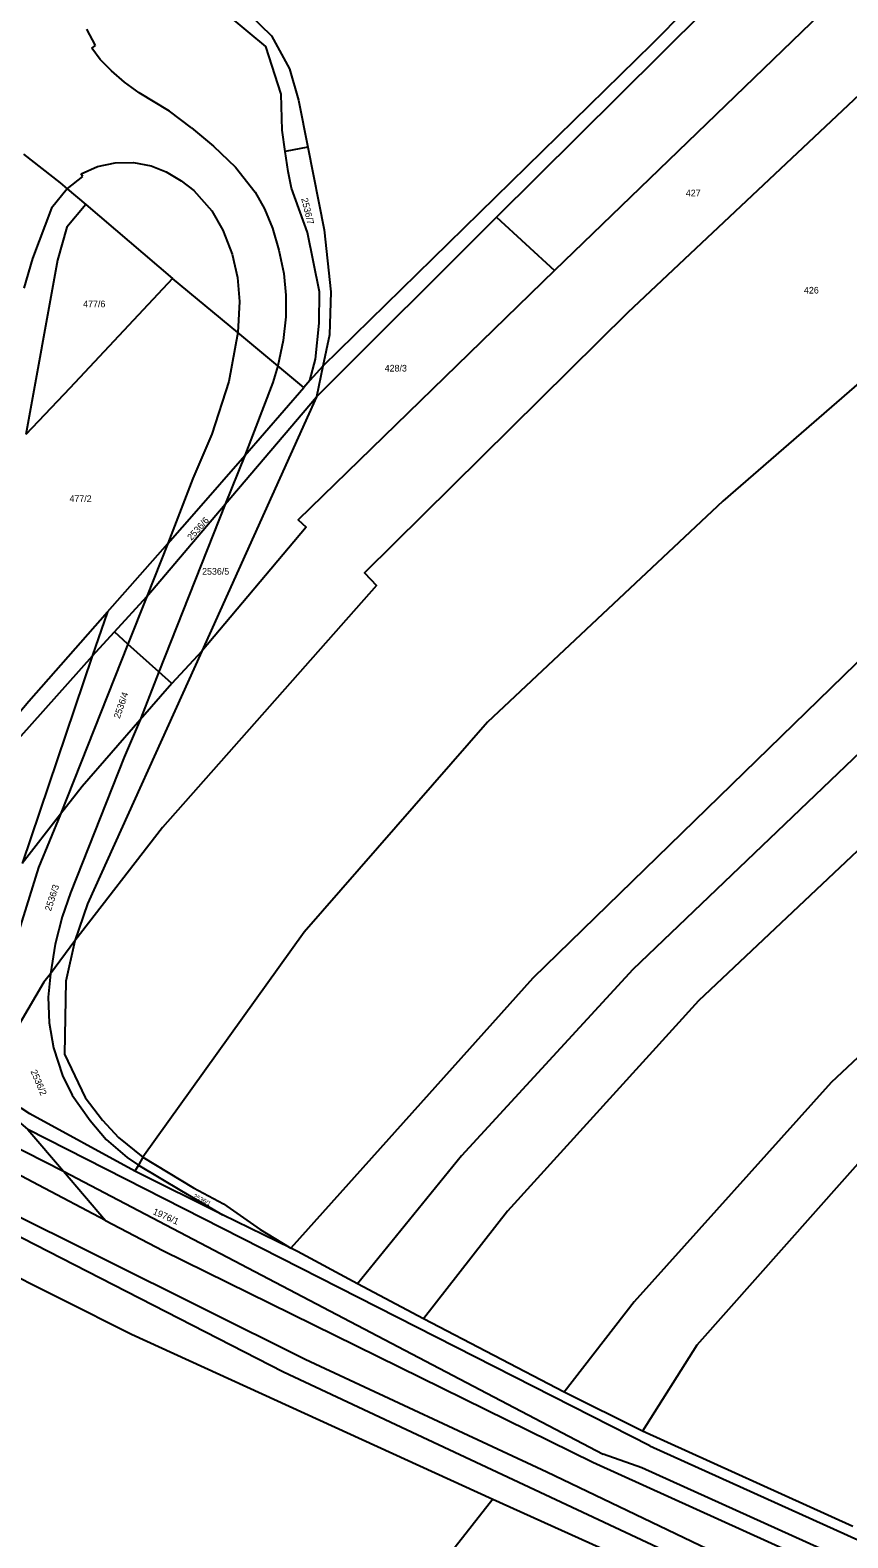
# Model space of a CAD drawing. Extents: x -679220 to -673243, y -1075091 to -1066557.
# Drawn here: x -675395.3 to -675185.8, y -1072555.7 to -1072169.3 of the extents above; entities that cross this region are included whole.
import ezdxf

# ---------------------------------------------------------------- set-up
doc = ezdxf.new("R2010")
doc.units = 0
for name, color, linetype in [('Hranice parcel', 7, 'Continuous'), ('Parcelní čísla', 7, 'Continuous'), ('Poz předměty', 7, 'Continuous'), ('Vnitřní kresba', 7, 'Continuous')]:
    doc.layers.add(name, color=color, linetype=linetype)

msp = doc.modelspace()

# ---------------------------------------------------------------- linework, layer by layer
at = {"layer": 'Hranice parcel'}
for p, q in [((-675324.2, -1072199.3), (-675329.94, -1072200.44)), ((-675381.09, -1072214.03), (-675358.84, -1072232.94)), ((-675321.99, -1072263.33), (-675275.85, -1072217.26)), ((-675275.85, -1072217.26), (-675260.93, -1072230.94)), ((-675320.31, -1072255.48), (-675323.63, -1072259.08)), ((-675320.31, -1072255.48), (-675321.99, -1072263.33)), ((-675323.63, -1072259.08), (-675325.19, -1072260.93)), ((-675321.99, -1072263.33), (-675351.33, -1072328.51)), ((-675375.49, -1072318.41), (-675379.42, -1072329.8)), ((-675379.42, -1072329.8), (-675373.72, -1072323.56)), ((-675379.42, -1072329.8), (-675413.96, -1072368.46)), ((-675379.42, -1072329.8), (-675397.36, -1072382.87)), ((-675351.33, -1072328.51), (-675359.05, -1072336.81)), ((-675294.51, -1072499.65), (-675311.42, -1072490.62)), ((-675258.46, -1072518.44), (-675294.51, -1072499.65)), ((-675238.38, -1072528.41), (-675258.46, -1072518.44)), ((-675184.55, -1072552.8), (-675238.38, -1072528.41))]:
    msp.add_line(p, q, dxfattribs=at)
for points in [[(-675275.85, -1072217.26), (-675244.41, -1072186.09), (-675178.48, -1072120.54), (-675145.94, -1072086.5), (-675117.65, -1072059.4), (-675100.56, -1072044.12)], [(-675329.94, -1072200.44), (-675330.72, -1072194.99), (-675330.99, -1072185.71), (-675334.96, -1072173.49), (-675339.5, -1072169.79), (-675348.13, -1072162.6), (-675353.01, -1072157.19), (-675356.64, -1072151.17), (-675358.93, -1072144.01), (-675360.73, -1072132.39), (-675360.41, -1072126.14), (-675357.75, -1072103.37), (-675354.88, -1072083.03), (-675353.44, -1072066.97), (-675352.22, -1072058.93)], [(-675352.22, -1072058.93), (-675352.59, -1072071.92), (-675358.06, -1072116.3), (-675356.74, -1072142.17), (-675354.71, -1072148.46), (-675350.97, -1072154.72), (-675344.89, -1072160.82), (-675339.37, -1072165.06), (-675333.49, -1072170.75), (-675328.88, -1072179.24), (-675326.6, -1072187.23), (-675324.2, -1072199.3)], [(-675081.54, -1072058.79), (-675158.69, -1072132.17), (-675260.93, -1072230.94)], [(-675062.83, -1072072.86), (-675177.11, -1072180.46), (-675242.21, -1072241.72), (-675309.68, -1072308.41), (-675306.57, -1072311.65), (-675361.42, -1072373.7), (-675383.87, -1072402.76)], [(-675016.61, -1072108.67), (-675072.82, -1072164.14), (-675217.81, -1072290.06), (-675278.13, -1072346.71), (-675325.12, -1072400.49), (-675366.42, -1072458.22)], [(-675200.87, -1072137.27), (-675235.99, -1072172.93), (-675320.31, -1072255.48)], [(-674996.61, -1072169.61), (-675087.12, -1072247.59), (-675177.44, -1072325.58), (-675266.51, -1072412.32), (-675328.57, -1072481.47)], [(-674985.52, -1072181.73), (-675082.08, -1072266.19), (-675178.64, -1072350.52), (-675240.9, -1072410.05), (-675284.84, -1072457.83), (-675311.42, -1072490.62)], [(-675324.2, -1072199.3), (-675320, -1072220.47), (-675318.26, -1072236.36), (-675318.59, -1072247.43), (-675320.31, -1072255.48)], [(-675397.04, -1072201.08), (-675387.67, -1072208.44), (-675385.83, -1072210), (-675381.09, -1072214.03)], [(-675323.63, -1072259.08), (-675322.24, -1072253.68), (-675321.3, -1072244.43), (-675321.18, -1072236.4), (-675324.22, -1072221.22), (-675328.36, -1072209.86), (-675329.21, -1072205.56), (-675329.94, -1072200.44)], [(-674985.89, -1072207.08), (-675077.27, -1072284.43), (-675144.18, -1072342.74), (-675224.09, -1072418.08), (-675273, -1072471.98), (-675294.51, -1072499.65)], [(-675381.09, -1072214.03), (-675385.95, -1072219.83), (-675388.33, -1072228.27), (-675396.42, -1072272.96)], [(-675358.84, -1072232.94), (-675385.17, -1072261.11), (-675396.42, -1072272.96)], [(-675325.19, -1072260.93), (-675331.86, -1072255.38), (-675342.14, -1072246.83), (-675358.84, -1072232.94)], [(-675260.93, -1072230.94), (-675326.64, -1072294.79), (-675324.58, -1072296.73), (-675351.33, -1072328.51)], [(-674964.57, -1072236.9), (-675089.77, -1072345), (-675190.07, -1072439.03), (-675240.52, -1072495.29), (-675258.46, -1072518.44)], [(-674957.78, -1072244.37), (-674951.67, -1072251.77), (-674996.15, -1072288.58), (-675077.89, -1072359.84), (-675131, -1072409.21), (-675179.24, -1072455.39), (-675224.47, -1072506.38), (-675238.38, -1072528.41)], [(-675375.49, -1072318.41), (-675360.07, -1072300.9), (-675352.69, -1072292.52), (-675340.32, -1072278.32), (-675325.19, -1072260.93)], [(-675373.72, -1072323.56), (-675365.42, -1072314.47), (-675345.34, -1072290.82), (-675321.99, -1072263.33)], [(-675412.53, -1072361.24), (-675395.68, -1072341.32), (-675375.49, -1072318.41)], [(-675359.05, -1072336.81), (-675362.35, -1072333.82), (-675370.26, -1072326.68), (-675373.72, -1072323.56)], [(-675351.33, -1072328.51), (-675380.6, -1072393.24), (-675383.87, -1072402.76)], [(-675359.05, -1072336.81), (-675367.17, -1072346.12), (-675382.04, -1072363.17), (-675387.58, -1072370.29), (-675397.36, -1072382.87)], [(-675383.87, -1072402.76), (-675390.15, -1072411.15), (-675391.78, -1072413.33), (-675401.43, -1072429.83), (-675402.97, -1072432.45)], [(-675383.87, -1072402.76), (-675386.16, -1072413.08), (-675386.51, -1072431.75), (-675381.24, -1072442.92), (-675376.78, -1072448.67), (-675372.71, -1072453.16), (-675366.42, -1072458.22)], [(-675399.54, -1072444.38), (-675401.42, -1072446.36), (-675395.88, -1072451.08), (-675386.77, -1072461.8), (-675376.04, -1072474.42)], [(-675368.49, -1072461.75), (-675395.42, -1072447.1), (-675397.67, -1072445.61)], [(-675376.04, -1072474.42), (-675393.22, -1072465.39), (-675420.5, -1072450.92)], [(-675366.42, -1072458.22), (-675367.6, -1072460.23), (-675368.49, -1072461.75)], [(-675366.42, -1072458.22), (-675353.49, -1072466.08), (-675345.78, -1072470.16), (-675336.4, -1072476.71), (-675328.57, -1072481.47)], [(-675328.57, -1072481.47), (-675346.08, -1072473), (-675368.49, -1072461.75)], [(-675432.05, -1072470.56), (-675405.5, -1072485.44), (-675369.37, -1072503.53), (-675276.78, -1072545.83)], [(-675376.04, -1072474.42), (-675361.34, -1072482.14), (-675251.13, -1072536.35), (-675159.57, -1072577.89), (-675152.01, -1072580.49), (-675136.3, -1072586.09), (-675119.02, -1072588.44), (-675082.82, -1072595.85), (-675017.97, -1072610.39)], [(-675311.42, -1072490.62), (-675326.84, -1072482.39), (-675328.57, -1072481.47)], [(-675276.78, -1072545.83), (-675293.61, -1072567.25), (-675312.81, -1072589.7), (-675320.66, -1072598.8), (-675370.78, -1072651.18)], [(-675276.78, -1072545.83), (-675186.13, -1072586.76), (-675132.39, -1072612.3)]]:
    msp.add_lwpolyline(points, dxfattribs=at)
at = {"layer": 'Poz předměty'}
for p, q in [((-675403.24, -1072470.9), (-675324.84, -1072509.99)), ((-675404.93, -1072474.99), (-675330.45, -1072513.19)), ((-675324.84, -1072509.99), (-675262.91, -1072538.86)), ((-675330.45, -1072513.19), (-675201.86, -1072573.42)), ((-675262.91, -1072538.86), (-675199.72, -1072569.07))]:
    msp.add_line(p, q, dxfattribs=at)
at = {"layer": 'Vnitřní kresba'}
for p, q in [((-675378.58, -1072173.25), (-675380.78, -1072169.03)), ((-675379.55, -1072173.9), (-675378.58, -1072173.25)), ((-675377.41, -1072176.85), (-675379.55, -1072173.9)), ((-675374.49, -1072179.73), (-675377.41, -1072176.85)), ((-675371.13, -1072182.63), (-675374.49, -1072179.73)), ((-675367.38, -1072185.37), (-675371.13, -1072182.63)), ((-675359.65, -1072190.12), (-675367.38, -1072185.37)), ((-675354.02, -1072194.35), (-675359.65, -1072190.12)), ((-675354.02, -1072194.35), (-675348.31, -1072199.02)), ((-675348.31, -1072199.02), (-675342.72, -1072204.43)), ((-675378.05, -1072204.29), (-675373.51, -1072203.36)), ((-675373.51, -1072203.36), (-675368.88, -1072203.26)), ((-675368.88, -1072203.26), (-675364.35, -1072204.07)), ((-675385.83, -1072210), (-675381.81, -1072206.87)), ((-675382.26, -1072206.16), (-675378.05, -1072204.29)), ((-675381.81, -1072206.87), (-675382.26, -1072206.16)), ((-675364.35, -1072204.07), (-675360.48, -1072205.62)), ((-675360.48, -1072205.62), (-675356.6, -1072207.92)), ((-675342.72, -1072204.43), (-675337.68, -1072210.86)), ((-675385.83, -1072210), (-675389.86, -1072214.95)), ((-675356.6, -1072207.92), (-675353.41, -1072210.39)), ((-675353.41, -1072210.39), (-675348.8, -1072215.66)), ((-675337.68, -1072210.86), (-675335.29, -1072215.13)), ((-675389.86, -1072214.95), (-675394.71, -1072227.86)), ((-675335.29, -1072215.13), (-675333.27, -1072220.1)), ((-675348.8, -1072215.66), (-675345.98, -1072220.6)), ((-675345.98, -1072220.6), (-675343.59, -1072226.7)), ((-675333.27, -1072220.1), (-675331.6, -1072225.73)), ((-675343.59, -1072226.7), (-675342.19, -1072232.72)), ((-675331.6, -1072225.73), (-675330.36, -1072231.67)), ((-675394.71, -1072227.86), (-675396.91, -1072235.45)), ((-675342.19, -1072232.72), (-675341.65, -1072238.87)), ((-675330.36, -1072231.67), (-675329.78, -1072237.23)), ((-675329.78, -1072237.23), (-675329.85, -1072242.81)), ((-675341.65, -1072238.87), (-675342.14, -1072246.83)), ((-675329.85, -1072242.81), (-675330.51, -1072248.85)), ((-675342.14, -1072246.83), (-675344.41, -1072259.38)), ((-675330.51, -1072248.85), (-675331.86, -1072255.38)), ((-675331.86, -1072255.38), (-675333.11, -1072259.63)), ((-675344.41, -1072259.38), (-675348.79, -1072272.84)), ((-675333.11, -1072259.63), (-675340.32, -1072278.32)), ((-675348.79, -1072272.84), (-675353.65, -1072284.25)), ((-675340.32, -1072278.32), (-675345.34, -1072290.82)), ((-675353.65, -1072284.25), (-675360.07, -1072300.9)), ((-675345.34, -1072290.82), (-675362.35, -1072333.82)), ((-675360.07, -1072300.9), (-675365.42, -1072314.47)), ((-675365.42, -1072314.47), (-675370.26, -1072326.68)), ((-675370.26, -1072326.68), (-675387.58, -1072370.29)), ((-675362.35, -1072333.82), (-675367.17, -1072346.12)), ((-675367.17, -1072346.12), (-675371.23, -1072355.62)), ((-675371.23, -1072355.62), (-675385, -1072390.39)), ((-675387.58, -1072370.29), (-675393.18, -1072383.9)), ((-675393.18, -1072383.9), (-675400.55, -1072407.56)), ((-675385, -1072390.39), (-675387.15, -1072396.61)), ((-675387.15, -1072396.61), (-675388.91, -1072403.55)), ((-675388.91, -1072403.55), (-675390.15, -1072411.15)), ((-675390.15, -1072411.15), (-675390.75, -1072417.16)), ((-675390.75, -1072417.16), (-675390.49, -1072423.74)), ((-675390.49, -1072423.74), (-675389.38, -1072430.14)), ((-675389.38, -1072430.14), (-675387.01, -1072437.24)), ((-675387.01, -1072437.24), (-675384.54, -1072442.27)), ((-675384.54, -1072442.27), (-675379.93, -1072448.81)), ((-675379.93, -1072448.81), (-675375.82, -1072453.65)), ((-675401.4, -1072454.31), (-675386.77, -1072461.8)), ((-675236.54, -1072532.18), (-675395.88, -1072451.08)), ((-675375.82, -1072453.65), (-675370.48, -1072458.25)), ((-675370.48, -1072458.25), (-675367.6, -1072460.23)), ((-675386.77, -1072461.8), (-675248.46, -1072534.32)), ((-675367.6, -1072460.23), (-675356.51, -1072466.79)), ((-675356.51, -1072466.79), (-675346.08, -1072473)), ((-675236.54, -1072532.18), (-675155.15, -1072568.93)), ((-675238.63, -1072537.82), (-675248.46, -1072534.32)), ((-675157.9, -1072574.25), (-675238.63, -1072537.82))]:
    msp.add_line(p, q, dxfattribs=at)

# ---------------------------------------------------------------- texts
at = {"layer": 'Parcelní čísla'}
for s, p in [('427', (-675227.32, -1072211.92)), ('426', (-675197.05, -1072236.82)), ('477/6', (-675381.75, -1072240.34)), ('428/3', (-675304.48, -1072256.81)), ('477/2', (-675385.26, -1072290.25)), ('2536/5', (-675351.27, -1072308.89))]:
    msp.add_text(s, height=1.7, dxfattribs=at).set_placement(p)
for s, height, rotation, p in [('2536/7', 1.7, 284, (-675325.88, -1072212.53)), ('2536/6', 1.7, 48, (-675354, -1072300.24)), ('2536/4', 1.7, 71, (-675372.38, -1072345.91)), ('2536/3', 1.7, 72, (-675390.01, -1072395.25)), ('2536/2', 1.7, 293, (-675395.27, -1072436.17)), ('2536/1', 1.14, 333, (-675353.65, -1072468.51)), ('1976/1', 1.7, 336, (-675364.05, -1072472.72))]:
    msp.add_text(s, height=height, rotation=rotation, dxfattribs=at).set_placement(p)

doc.saveas('drawing.dxf')
